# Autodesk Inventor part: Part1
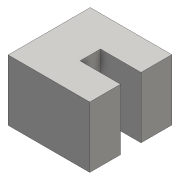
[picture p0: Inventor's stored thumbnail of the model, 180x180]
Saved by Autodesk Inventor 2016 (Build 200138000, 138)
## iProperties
Created: 2015-07
Part Number: Part1
Material: Generic
Document SubType Name: Modeling
Designer: Sandeep
Density: 1 g/cm^3
Appearance: Default
Author: Sandeep
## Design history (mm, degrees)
sketch "Sketch1"
  geometry: L1 (0, 0)-(-30, 0); L2 (-30, 0)-(-30, 40); L3 (-30, 40)-(0, 40); L4 (0, 40)-(0, 0)
  constraints: 8 end point, 2 parallel, 1 horizontal, 1 perpendicular
  dimensions: "d0" = 30 distance between parallel lines of L4 L2; "d1" = 40 distance of L1.end L2.end
extrude "Extrusion1" new body sketch "Sketch1" distance "d2" = 20; taper "d3" = 0 deg
sketch "Sketch2"
  geometry: L1 (0, 40)-(0, 0) reference; L2 (-20, 0)-(-20, 40) reference; L3 (0, 0)-(-20, 0) reference; L4 (-20, 15)-(0, 15); L5 (0, 15)-(0, 25); L6 (0, 25)-(-20, 25); L7 (-20, 25)-(-20, 15)
  constraints: 8 end point, 2 parallel, 2 point on line, 1 horizontal, 1 perpendicular
  dimensions: "d4" = 10 distance between parallel lines of L6 L4; "d5" = 15 distance between parallel lines of L3 L4
extrude "Extrusion2" cut sketch "Sketch2" distance "d6" = 10; taper "d7" = 0 deg
node "Direct Edit1"
body "Solid1"
feature "Size1" dims "d8" = 9.75
